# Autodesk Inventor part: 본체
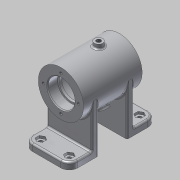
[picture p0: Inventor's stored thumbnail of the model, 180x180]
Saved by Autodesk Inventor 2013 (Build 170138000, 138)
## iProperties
Created: 2017-02
Part Number: 본체
Material: 알루미늄 6061
Document SubType Name: Modeling
Designer: Administrator
Mass: 355.288 g
Surface Area: 424.021 cm^2
Volume: 131.103 cm^3
Density: 2.71 g/cm^3
Author: Administrator
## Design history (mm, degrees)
sketch "스케치2"
  geometry: L1 (0, 16)-(0, 27); L2 (0, 27)-(70, 27); L3 (0, 16)-(12, 16); L4 (12, 16)-(12, 14); L5 (12, 14)-(15, 14); L6 (15, 14)-(15, 22); L7 (15, 22)-(55, 22); L8 (55, 22)-(55, 14); L9 (55, 14)-(58, 14); L10 (58, 14)-(58, 16); L11 (58, 16)-(70, 16); L12 (70, 16)-(70, 27); L13 (0, 0)-(70, 0)
  constraints: 26 end point, 7 perpendicular, 5 parallel, 1 point on line, 1 vertical
  dimensions: "d0" = 54 diameter of L2 L13; "d2" = 12 distance between parallel lines of L4 L1; "d3" = 12 distance between parallel lines of L12 L10; "d4" = 70 distance between parallel lines of L1 L12; "d5" = 40 distance between parallel lines of L8 L6; "d6" = 3 distance between parallel lines of L6 L4; "d7" = 32 diameter of L3 L13; "d8" = 44 diameter of L7 L13; "d9" = 28 diameter of L5 L13; "d10" = 28 diameter of L9 L13; "d11" = 32 diameter of L11 L13; "d12" = 70 distance of L13.start L13.end
revolve "회전1" sketch "스케치2" stored, may be unused: angle "d13" = 90 deg
node "작업 평면1"
sketch "스케치3"
  geometry: L1 (27, 70)-(-27, 70) reference; C1 r 5 at (0, 45); 1 further point
  constraints: 1 centre point, 1 vertical alignment
  dimensions: "d16" = 10 diameter of C1; "d121" = 25 distance from line of C1.centre L1
extrude "돌출1" join sketch "스케치3" stored distance "d17" = 10; taper "d18" = 0 deg
sketch "스케치4"
  geometry: C1 r 5 at (0, 0) reference; 1 further point
hole "구멍1" sketch "스케치4" at (0, 0) diameter "d19" = 5.242; stored, may be unused: countersink angle "d23" = 90 deg, drill point angle "d25" = 118 deg; dims "d20" = 6, "d21" = 4, "d22" = 2, "d24" = 8
node "작업 평면2"
sketch "스케치5"
  geometry: L1 (0, 0)-(16.339, -25.16); L2 (0, 0)-(0, -27)
  constraints: 4 end point, 1 vertical, 1 vertical alignment, 1 other
  dimensions: "d26" = 30 distance of L1.start L1.end; "d27" = 33 deg angle of L2 L1
node "작업 평면3"
sketch "스케치6"
  geometry: C1 r 6 at (0, 0); 1 further point
  constraints: 1 centre point
  dimensions: "d28" = 12 diameter of C1
extrude "돌출2" join sketch "스케치6" stored distance "d30" = 10; taper "d31" = 0 deg
sketch "스케치7"
  geometry: C1 r 6 at (0, 0) reference; C2 r 3 at (0, 0); 1 further point
  constraints: 1 centre point, 1 coincident
  dimensions: "d32" = 6 diameter of C2
hole "구멍2" sketch "스케치7" at (0, 0) diameter "d34" = 5.242; stored, may be unused: countersink angle "d38" = 90 deg, drill point angle "d40" = 118 deg; dims "d35" = 6, "d36" = 4, "d37" = 2, "d39" = 8
node "작업 평면4"
sketch "스케치8"
  geometry: L1 (27, 0)-(-27, 0) reference; L2 (27, 70)-(-27, 70) reference; L3 (0, 70)-(0, 0); L4 (0, 35)-(-27, 35); L5 (-27, 87)-(27, 87); L6 (27, -17)-(-27, -17); L7 (-27, 52)-(27, 52); L8 (-27, 87)-(-27, 52); L9 (27, 52)-(27, 87); L10 (27, 18)-(-27, 18); L11 (-27, -17)-(-27, 18); L12 (27, 18)-(27, -17); 2 further points
  constraints: 20 end point, 5 parallel, 5 perpendicular, 2 midpoint, 1 horizontal, 1 point on line, 2 other
  dimensions: "d48" = 104 distance between parallel lines of L6 L5; "d49" = 52 distance between parallel lines of L5 L4; "d50" = 27 distance between parallel lines of L3 L8; "d51" = 27 distance between parallel lines of L11 L3; "d52" = 54 distance between parallel lines of L9 L8; "d53" = 17 distance between parallel lines of L4 L7; "d54" = 27 distance of L4.start L4.end; "d55" = 17 distance between parallel lines of L10 L4
extrude "돌출3" join sketch "스케치8" distance "d56" = 8; taper "d57" = 0 deg
fillet "모깎기1" dims "d58" = 10
sketch "스케치9"
  geometry: L1 (27, -7)-(27, 18) reference; L2 (27, 18)-(-27, 18) reference; L3 (-17, 87)-(17, 87) reference; L4 (27, 77)-(27, 52) reference; L5 (27, 52)-(-27, 52) reference; L6 (-27, 52)-(-27, 77) reference; L7 (-27, 18)-(27, 18); L8 (27, 18)-(27, 10); L9 (27, 10)-(-27, 10); L10 (-27, 10)-(-27, 18); L11 (-27, 52)-(27, 52); L12 (27, 52)-(27, 60); L13 (27, 60)-(-27, 60); L14 (-27, 60)-(-27, 52); A1 r 10 centre (-17, 77) between (-17, 87) and (-27, 77) reference; A2 r 10 centre (17, 77) between (27, 77) and (17, 87) reference; 1 further point
  constraints: 16 end point, 4 parallel, 2 horizontal, 2 perpendicular, 2 point on line
  dimensions: "d59" = 8 distance between parallel lines of L11 L13; "d61" = 8 distance between parallel lines of L9 L2
extrude "돌출4" join sketch "스케치9" stored distance "d62" = 8; taper "d63" = 0 deg
sketch "스케치10" dims "d64" = 9
  geometry: L1 (-21.5, -4.402)-(-17, -1.804); L2 (-17, -1.804)-(-12.5, -4.402); L3 (-12.5, -4.402)-(-12.5, -9.598); L4 (-12.5, -9.598)-(-17, -12.196); L5 (-17, -12.196)-(-21.5, -9.598); L6 (-21.5, -9.598)-(-21.5, -4.402); A1 r 10 centre (-17, -7) between (-27, -7) and (-17, -17) reference; 4 further points
  constraints: 12 end point, 2 coincident, 2 horizontal alignment, 1 midpoint, 15 other
extrude "돌출5" cut sketch "스케치10" distance "d66" = 3; taper "d67" = 0 deg
sketch "스케치11"
  geometry: L1 (-21.5, -4.402)-(-17, -1.804) reference; L2 (-21.5, -9.598)-(-21.5, -4.402) reference; L3 (-17, -12.196)-(-21.5, -9.598) reference; L4 (-12.5, -9.598)-(-17, -12.196) reference; L5 (-12.5, -4.402)-(-12.5, -9.598) reference; L6 (-17, -1.804)-(-12.5, -4.402) reference; C1 r 2.5 at (-17, -7); A1 r 10 centre (-17, -7) between (-27, -7) and (-17, -17) reference; 1 further point
  constraints: 1 centre point, 1 coincident
  dimensions: "d68" = 5 diameter of C1
extrude "돌출6" cut sketch "스케치11" stored distance "d70" = 3; taper "d71" = 0 deg
fillet "모깎기2" dims "d72" = 2
fillet "모깎기3" dims "d79" = 2
fillet "모깎기4" dims "d80" = 2
fillet "모깎기5" dims "d81" = 2
fillet "모깎기6" dims "d82" = 0.3
fillet "모깎기7" dims "d83" = 2
sketch "스케치12" dims "d84" = 42
  geometry: C1 r 27 at (0, 0) reference; C2 r 16 at (0, 0) reference; C3 r 2.5 at (0, 21); 1 further point
  constraints: 2 vertical alignment, 1 centre point, 1 coincident, 2 other
  dimensions: "d86" = 5 diameter of C3
hole "구멍3" sketch "스케치12" at (0, 21) diameter "d87" = 3.242; stored, may be unused: countersink angle "d91" = 90 deg, drill point angle "d93" = 118 deg; dims "d88" = 8, "d89" = 4, "d90" = 2, "d92" = 10
sketch "스케치13"
  geometry: C1 r 1.621 at (0, -21) reference
hole "구멍4" sketch "스케치13" at (0, -21) diameter "d97" = 3.242; stored, may be unused: countersink angle "d101" = 90 deg, drill point angle "d103" = 118 deg; dims "d98" = 8, "d99" = 4, "d100" = 2, "d102" = 10
chamfer "모따기1" distance "d107" = 1; stored, may be unused: second distance "d108" = 2, angle "d109" = 45 deg
fillet "모깎기8" dims "d110" = 3
node "작업 평면5"
node "작업 평면6"
sketch "스케치15"
  geometry: L1 (-51.946, 2.402)-(-18.054, 2.402); L2 (-18.054, 2.402)-(-18.054, -2.402); L3 (-18.054, -2.402)-(-51.946, -2.402); L4 (-51.946, -2.402)-(-51.946, 2.402); L5 (-51.946, 0)-(-18.054, 0); L6 (-35, 2.402)-(-35, -2.402); L7 (0, 27)-(-70, 27) reference; L8 (-70, 27)-(-70, -27) reference; 1 further point
  constraints: 4 end point, 4 midpoint, 2 other
  dimensions: "d117" = 27 distance between parallel lines of L5 L7; "d118" = 35 distance between parallel lines of L8 L6
feature "엠보싱2" sketch "스케치15" dims "d17" = 10, "d18" = 0, "d119" = 0.5, "d120" = 0
node "솔리드1"
pattern_linear "직사각형 패턴1" dims "d75" = 34, "d78" = 84
pattern_circular "원형 패턴1" dims angle "d95" = 360 deg
pattern_circular "원형 패턴2" dims angle "d105" = 360 deg
node "투영된 루프1"
node "투영된 루프2"
node "투영된 루프3"
other parameters: "d14" = 32, "d111" = 58.5, "d116" = -96.75
